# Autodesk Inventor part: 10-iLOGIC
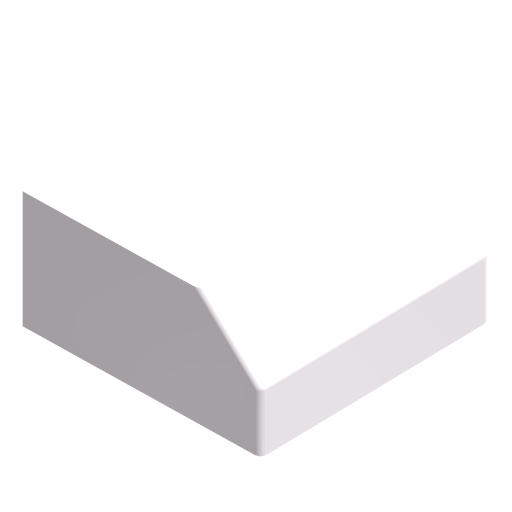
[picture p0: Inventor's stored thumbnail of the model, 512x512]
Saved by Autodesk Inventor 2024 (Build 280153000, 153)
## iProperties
Company: ATC
RuleStatus: InUse
Created: 2023-03
Part Number: 10-iLOGIC
Document SubType Name: Modeling
Designer: Andrzej Jaskulski
Material: Kurs-AJ
Density: 1 g/cm^3
Mass: 29.9888 g
Surface Area: 60.4223 cm^2
Volume: 29.9888 cm^3
Appearance: Kurs-AJ
Checked By: A.J.
Engr Approved By: Andrzej Jaskulski
Mfg Approved By: Andrzej Jaskulski
Authority: A.J.
Control State: 0
Master: False
Checked Out: False
Shininess: 0.0
Length Units: 11269
Angle Units: 11279
Time Units: 11290
Mass Units: 11283
Length Display Precision: 3
Angle Display Precision: 2
Compacted: True
WYS: 20.0
BOK: 40,000 mm
Density: 0.0
Volumn: 0.0
Area: 0.0
PropertySet Name: Model Information
Title: A.J.: Kurs R2024-MEP
Author: Andrzej Jaskulski
Revision Number: 1/24
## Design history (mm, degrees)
node "BAZA" dims "d0" = 0
  sketch "Podstawa"
    geometry: L1 (-17.508, -1.693)-(-18.315, 38.299); L2 (-18.315, 38.299)-(-58.307, 37.492); L3 (-58.307, 37.492)-(-57.5, -2.5); L4 (-57.5, -2.5)-(-17.508, -1.693)
    constraints: 8 end point, 2 parallel, 2 perpendicular, 2 other
node "Fazowanie 10 mm" dims "d4" = 10, "d5" = 10, "d30" = 45 deg
node "Zaokrąglenie 1 mm" dims "R" = 1
node "Bryła1"
node "Korpusy bryłowe"
node "Korpusy powierzchniowe"
